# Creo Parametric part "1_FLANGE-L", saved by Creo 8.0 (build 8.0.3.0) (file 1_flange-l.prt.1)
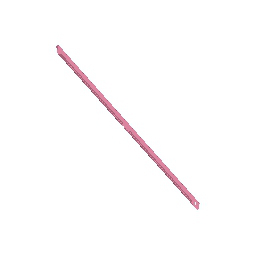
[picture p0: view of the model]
Units: millimeter Newton Second (mmNs); MM, TONNE, SECS

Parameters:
  SMT_DFLT_BEND_REL_LENGTH_TYPE = "Through All"

Other parameters: SMT_UPDATE_BEND_ALLOW_INFO, SMT_THICKNESS, SMT_PART_BEND_ALLOWANCE_FACTOR, SMT_DFLT_BEND_RADIUS, SMT_DFLT_BEND_ANGLE, SMT_DFLT_CRNR_REL_WIDTH, SMT_DFLT_CRNR_REL_DEPTH, SMT_DFLT_BEND_REL_WIDTH, SMT_DFLT_BEND_REL_DEPTH, SMT_DFLT_BEND_REL_LENGTH, SMT_DFLT_BEND_REL_ANGLE, SMT_GAP, SMT_DFLT_EDGE_TREA_WIDTH, SMT_DFLT_MITER_CUT_WIDTH, SMT_DFLT_MITER_CUT_OFFSET

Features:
  1. datum plane "RIGHT"
  2. datum plane "TOP"
  3. datum plane "FRONT"
  4. coordinate system
  5. pattern
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
Other named items: COPIED_GROUP, COPIED_GROUP_1, COPIED_GROUP_3

Layers: 0_ALL_AXIS, 0_ALL_CSYS, 0_ALL_CURVES, 0_ALL_PLANES, 0_ALL_POINTS, 0_ALL_SURFS, 1_FLANGE-L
